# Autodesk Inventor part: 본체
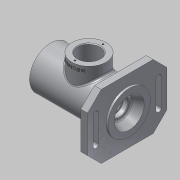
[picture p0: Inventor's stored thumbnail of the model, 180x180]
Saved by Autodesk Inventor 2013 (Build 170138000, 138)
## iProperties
Created: 2017-10
Part Number: 본체
Material: 알루미늄 6061
Document SubType Name: Modeling
Designer: dgall
Density: 1 g/cm^3
Author: dgall
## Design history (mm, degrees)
sketch "스케치1"
  geometry: L1 (0, 0)-(115, 0); L2 (0, 20)-(9, 20); L3 (9, 20)-(9, 24); L4 (9, 24)-(12, 24); L5 (12, 24)-(12, 20); L6 (12, 20)-(21, 20); L7 (21, 20)-(21, 17.5); L8 (21, 17.5)-(24.25, 17.5); L9 (24.25, 17.5)-(24.25, 18.5); L10 (24.25, 18.5)-(26, 18.5); L11 (26, 18.5)-(26, 16.5); L12 (26, 16.5)-(37, 16.5); L13 (37, 16.5)-(37, 26); L14 (75, 26)-(75, 17.5); L15 (75, 17.5)-(86, 17.5); L16 (86, 17.5)-(86, 16.5); L17 (86, 16.5)-(91, 16.5); L18 (91, 16.5)-(91, 10); L19 (91, 10)-(93.7, 10); L20 (93.7, 10)-(93.7, 12.5); L21 (93.7, 12.5)-(101, 12.5); L22 (101, 12.5)-(101, 16); L23 (101, 16)-(115, 22); L24 (0, 20)-(0, 31); L25 (0, 31)-(115, 31); L26 (115, 31)-(115, 22); L27 (37, 26)-(75, 26)
  constraints: 54 end point, 21 parallel, 3 perpendicular, 1 collinear, 1 horizontal, 1 vertical alignment
  dimensions: "d0" = 115 distance of L1.start L1.end; "d1" = 62 diameter of L25 L1; "d2" = 48 diameter of L4 L1; "d3" = 40 diameter of L6 L1; "d4" = 40 diameter of L2 L1; "d5" = 35 diameter of L8 L1; "d6" = 37 diameter of L10 L1; "d7" = 33 diameter of L12 L1; "d8" = 44 diameter of L23.end L1; "d9" = 32 diameter of L22.end L1; "d10" = 25 diameter of L21 L1; "d11" = 20 diameter of L19 L1; "d13" = 33 diameter of L17 L1; "d14" = 35 diameter of L15 L1; "d16" = 52 diameter of L27 L1; "d17" = 38 distance of L13.end L14.start; "d18" = 115 distance between parallel lines of L24 L26; "d20" = 3 distance of L3.end L4.end; "d21" = 12 distance between parallel lines of L24 L5; "d22" = 21 distance between parallel lines of L24 L7; "d23" = 26 distance between parallel lines of L24 L11; "d24" = 1.75 distance of L9.end L10.end; "d25" = 11 distance of L11.end L12.end; "d27" = 60 distance of L11.end L16.end; "d28" = 5 distance from line of L18 L15.end; "d29" = 14 horizontal distance of L22.end L23.end; "d30" = 2.7 distance of L18.end L19.end
revolve "회전1" sketch "스케치1" stored, may be unused: angle "d31" = 90 deg
node "작업 평면1"
sketch "스케치2"
  geometry: C1 r 25 at (56, 0); 1 further point
  constraints: 1 centre point, 1 horizontal alignment
  dimensions: "d33" = 56 distance of point (0, 0) C1.centre; "d34" = 50 diameter of C1
extrude "돌출1" join sketch "스케치2" stored distance "d35" = 10; taper "d36" = 0 deg
sketch "스케치3"
  geometry: C1 r 25 at (0, 0) reference; C2 r 16 at (0, 0); 1 further point
  constraints: 1 centre point, 1 coincident
  dimensions: "d37" = 32 diameter of C2
extrude "돌출2" cut sketch "스케치3" stored distance "d39" = 10; taper "d40" = 0 deg
node "작업 평면2"
sketch "스케치5"
  geometry: L1 (47, -58)-(-47, -58); L2 (-47, -58)-(-47, 58); L3 (-47, 58)-(47, 58); L4 (47, 58)-(47, -58); L5 (47, -58)-(-47, 58); L6 (-47, -58)-(47, 58); C1 r 31 at (0, 0) reference; C2 r 20.714 at (0, 0) reference; C3 r 31 at (0, 0) reference; C4 r 20.714 at (0, 0) reference; 1 further point
  constraints: 12 end point, 2 midpoint, 2 parallel, 1 horizontal, 1 perpendicular
  dimensions: "d42" = 94 distance of L1.start L1.end; "d44" = 116 distance of L3.end L1.start
extrude "돌출3" join sketch "스케치5" distance "d45" = 10; taper "d46" = 0 deg
chamfer "모따기1" distance "d47" = 20; stored, may be unused: second distance "d48" = 2, angle "d49" = 45 deg
sketch "스케치6"
  geometry: L1 (20, 50)-(-20, 50); L2 (20, 42)-(-20, 42); C1 r 31 at (0, 0) reference; A1 r 4 centre (20, 46) between (20, 42) and (20, 50); A2 r 4 centre (-20, 46) between (-20, 50) and (-20, 42)
  constraints: 4 end point, 4 point on circle, 4 tangent, 2 centre point, 1 equal radius
  dimensions: "d50" = 46 vertical distance of C1.centre A1.centre; "d51" = 46 vertical distance of A2.centre C1.centre; "d52" = 8 diameter of A1; "d53" = 20 horizontal distance of A2.centre C1.centre; "d54" = 20 horizontal distance of C1.centre A1.centre
extrude "돌출4" cut sketch "스케치6" stored distance "d55" = 10; taper "d56" = 0 deg
node "작업 평면3"
sketch "스케치7" dims "d57" = 41
  geometry: C1 r 16 at (0, 0) reference; C2 r 25 at (0, 0) reference; 3 further points
  constraints: 2 vertical alignment, 1 coincident, 2 other
hole "구멍1" sketch "스케치7" at (0, 20.5) diameter "d59" = 2.459; stored, may be unused: countersink angle "d63" = 90 deg, drill point angle "d65" = 118 deg; dims "d60" = 6, "d61" = 4, "d62" = 2, "d64" = 8
fillet "모깎기1" dims "d69" = 3
fillet "모깎기2" dims "d70" = 3
chamfer "모따기2" distance "d71" = 1; stored, may be unused: second distance "d72" = 2, angle "d73" = 45 deg
fillet "모깎기3" dims "d74" = 3
fillet "모깎기4" dims "d75" = 3
fillet "모깎기5" dims "d76" = 0.3
fillet "모깎기6" dims "d80" = 3
chamfer "모따기4" distance "d81" = 0.5; stored, may be unused: second distance "d82" = 2, angle "d83" = 60 deg
node "작업 평면4"
sketch "스케치14"
  geometry: L1 (39.408, 43.402)-(72.592, 43.402); L2 (72.592, 43.402)-(72.592, 38.598); L3 (72.592, 38.598)-(39.408, 38.598); L4 (39.408, 38.598)-(39.408, 43.402); L5 (0, 31)-(99, 31) reference; L6 (31, 47)-(81, 47) reference; L7 (39.408, 41)-(72.592, 41); L8 (56, 43.402)-(56, 38.598); 1 further point
  constraints: 4 end point, 4 midpoint, 2 other
  dimensions: "d86" = 56 distance from line of L5.start L8; "d87" = 10 distance between parallel lines of L5 L7
feature "엠보싱1" sketch "스케치14" dims "d0" = 115, "d1" = 62, "d2" = 48, "d3" = 40, "d4" = 40, "d5" = 35, "d6" = 37, "d7" = 33, "d8" = 44, "d9" = 32, "d10" = 25, "d11" = 20, "d13" = 33, "d14" = 35, "d16" = 52, "d17" = 38, "d18" = 115, "d20" = 3, "d21" = 12, "d22" = 21, "d23" = 26, "d24" = 1.75, "d25" = 11, "d27" = 60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
feature "스레드2" dims "d92" = 10, "d93" = 0
chamfer "모따기5" distance "d94" = 1; stored, may be unused: second distance "d95" = 2, angle "d96" = 45 deg
node "솔리드1"
mirror "대칭1"
pattern_circular "원형 패턴1" dims angle "d67" = 360 deg
node "절단 모서리 투영1"
node "절단 모서리 투영2"
other parameters: "d32" = 47, "d41" = -3, "d84" = -25.3
